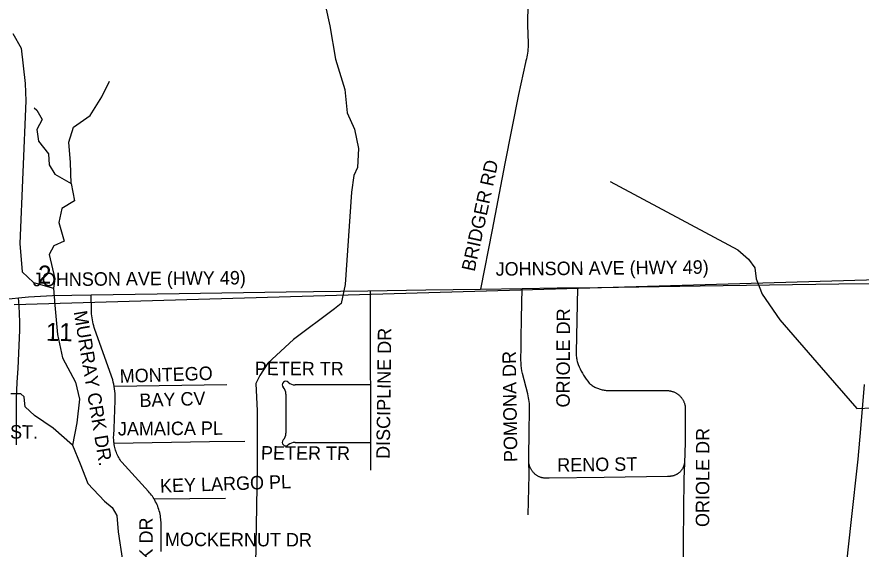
# Model space of a CAD drawing. Extents: x 1670563 to 1761545, y 515755 to 578944.
# Drawn here: x 1715137 to 1719841, y 558581 to 561545 of the extents above; entities that cross this region are included whole.
import ezdxf

# ---------------------------------------------------------------- set-up
doc = ezdxf.new("R2010")
doc.units = 0
for name, color, linetype in [('5_sectionlines', 7, 'Continuous'), ('62_text', 7, 'Continuous'), ('SHP_LINE', 7, 'Continuous'), ('STREETCL', 7, 'Continuous'), ('STRNAMES', 7, 'Continuous')]:
    doc.layers.add(name, color=color, linetype=linetype)

msp = doc.modelspace()

# ---------------------------------------------------------------- linework, layer by layer
at = {"layer": '5_sectionlines'}
msp.add_lwpolyline([(1715121.2, 559943.8), (1720383.9, 560096.2), (1725635, 560117.2)], dxfattribs=at)
at = {"layer": 'SHP_LINE'}
for points in [[(1716829, 561733), (1716881, 561495), (1716913, 561309), (1716965, 561140), (1716977, 561011), (1717018, 560920), (1717040, 560812), (1717035, 560706), (1717014, 560661), (1717001, 560568), (1716966, 560055), (1716944, 559949), (1716907, 559919), (1716678, 559748), (1716535, 559616), (1716490, 559547), (1716468, 559504), (1716476, 559352), (1716476, 559038), (1716456, 557842)], [(1715114, 561452), (1715161, 561370), (1715183, 561174), (1715188, 561078), (1715153, 560282), (1715166, 560125), (1715230, 560066), (1715342, 560035)], [(1715440, 560617), (1715436, 560734), (1715427, 560847), (1715453, 560930), (1715545, 560995), (1715610, 561100), (1715654, 561187)], [(1715233, 561039), (1715249, 561026), (1715279, 560974), (1715249, 560917), (1715257, 560852), (1715314, 560782), (1715318, 560721), (1715349, 560669), (1715440, 560617)], [(1715440, 560617), (1715458, 560521), (1715388, 560477), (1715371, 560399), (1715401, 560295), (1715344, 560269), (1715318, 560221), (1715349, 560086), (1715342, 560035)], [(1718442, 560629), (1719154, 560248), (1719214, 560196), (1719248, 560147), (1719256, 560087), (1719290, 560000), (1719388, 559857), (1719618, 559593), (1719817, 559364), (1719904, 559368)], [(1715342, 560035), (1715348, 559939), (1715363, 559776), (1715391, 559647), (1715464, 559511), (1715487, 559417), (1715471, 559285), (1715448, 559160)], [(1715448, 559160), (1715339, 559255), (1715236, 559325), (1715183, 559373), (1715179, 559408), (1715178, 559430), (1715159, 559445), (1715104, 559445)], [(1715448, 559160), (1715489, 559056), (1715533, 558946), (1715625, 558849), (1715669, 558813), (1715694, 558769), (1715702, 558677), (1715726, 558518), (1715752, 558442), (1715750, 558388), (1715770, 558340), (1715754, 558253), (1715745, 558154), (1715781, 558044), (1715853, 557990), (1715937, 557973), (1715999, 557974), (1716056, 557940), (1716130, 557887), (1716243, 557864), (1716330, 557869), (1716391, 557866), (1716456, 557842)]]:
    msp.add_lwpolyline(points, dxfattribs=at)
at = {"layer": 'STREETCL'}
for points in [[(1717986.7, 561877.2), (1717982.5, 561498.3), (1717985.3, 561397.7), (1717985.4, 561386.8), (1717985.1, 561375.8), (1717984.5, 561364.9), (1717983.5, 561354.1), (1717982.2, 561343.2), (1717980.5, 561332.5), (1717978.4, 561321.7), (1717975.9, 561311.1), (1717973.1, 561300.6), (1717970, 561290.1), (1717932.5, 561112.4), (1717856, 560728.7), (1717785.7, 560358.8), (1717720.8, 560029)], [(1717092.5, 560020), (1717415.9, 560024.7), (1717720.8, 560029)], [(1717720.8, 560029), (1717952.4, 560032.4)], [(1717989.1, 559074.8), (1717991.2, 559250.6), (1717992.9, 559336.1), (1717993.4, 559347.2), (1717993.6, 559358.2), (1717993.5, 559369.3), (1717993.1, 559380.4), (1717992.3, 559391.5), (1717991.2, 559402.5), (1717989.7, 559413.5), (1717987.8, 559424.4), (1717985.6, 559435.3), (1717983.1, 559446.1), (1717953.6, 559559.2), (1717950.9, 559573.9), (1717948.7, 559588.6), (1717946.9, 559603.4), (1717945.8, 559618.2), (1717945.1, 559633.1), (1717944.9, 559648), (1717945.2, 559662.9), (1717946.1, 559677.7), (1717946.7, 559754), (1717947.8, 559864.4), (1717952.4, 560032.4)], [(1717952.4, 560032.4), (1718147.5, 560035.2), (1718259.7, 560036.7)], [(1718259.7, 560036.7), (1718252.9, 559675.4), (1718252.9, 559669.3), (1718253.1, 559663.1), (1718253.5, 559656.9), (1718254.2, 559650.8), (1718255, 559644.7), (1718256.1, 559638.6), (1718257.3, 559632.6), (1718258.8, 559626.6), (1718260.5, 559620.7), (1718262.4, 559614.8), (1718264.5, 559609), (1718269.7, 559596.7), (1718275.3, 559584.6), (1718281.3, 559572.6), (1718287.7, 559560.9), (1718294.5, 559549.4), (1718301.7, 559538.1), (1718309.2, 559527.1), (1718317.2, 559516.4), (1718325.4, 559505.9), (1718329.6, 559502.3), (1718333.8, 559498.8), (1718338.2, 559495.4), (1718342.7, 559492.3), (1718347.3, 559489.2), (1718352, 559486.4), (1718356.7, 559483.7), (1718361.6, 559481.1), (1718366.6, 559478.8), (1718371.6, 559476.6), (1718376.8, 559474.6), (1718381.9, 559472.8), (1718387.2, 559471.1), (1718392.5, 559469.7), (1718397.8, 559468.4), (1718403.2, 559467.3), (1718408.6, 559466.4), (1718414.1, 559465.7), (1718419.6, 559465.2), (1718425, 559464.8), (1718430.5, 559464.7), (1718760.3, 559464), (1718763.9, 559463.8), (1718767.4, 559463.6), (1718770.9, 559463.2), (1718774.4, 559462.8), (1718777.8, 559462.2), (1718781.3, 559461.4), (1718784.7, 559460.6), (1718788.1, 559459.6), (1718791.5, 559458.6), (1718794.8, 559457.4), (1718798.1, 559456.1), (1718801.3, 559454.7), (1718804.5, 559453.2), (1718807.6, 559451.5), (1718810.6, 559449.8), (1718813.7, 559448), (1718816.6, 559446), (1718819.5, 559444), (1718822.3, 559441.9), (1718825, 559439.6), (1718827.6, 559437.3), (1718830.2, 559434.9), (1718832.7, 559432.4), (1718835.1, 559429.8), (1718837.4, 559427.2), (1718839.6, 559424.4), (1718841.7, 559421.6), (1718843.7, 559418.7), (1718845.7, 559415.8), (1718847.5, 559412.7), (1718849.2, 559409.7), (1718850.8, 559406.5), (1718852.3, 559403.3), (1718853.7, 559400.1), (1718855, 559396.8), (1718856.1, 559393.5), (1718857.2, 559390.1), (1718858.1, 559386.7), (1718858.9, 559383.3), (1718859.6, 559379.9), (1718860.2, 559376.4), (1718860.7, 559372.9), (1718861, 559369.4), (1718861.2, 559365.9), (1718861.2, 559250.4), (1718859.5, 559174.7), (1718856.2, 559059.5)], [(1718259.7, 560036.7), (1718944, 560046.4), (1719715.7, 560057.7), (1719906.5, 560060.3)], [(1712480.7, 558684.6), (1712572.9, 558740.6), (1712940.5, 558965.5), (1713388.6, 559240.4), (1713771.7, 559474.8), (1714010.2, 559617.7), (1714063.8, 559648.6), (1714118.5, 559677.9), (1714174, 559705.3), (1714230.4, 559730.9), (1714287.6, 559754.7), (1714403.4, 559798.6), (1714520.5, 559839.1), (1714638.7, 559876.1), (1714758, 559909.6), (1714878.2, 559939.6), (1714910.1, 559946.5), (1714942.2, 559952.4), (1714974.5, 559957.3), (1715007, 559961.1), (1715076.4, 559972.2), (1715146.1, 559980.9)], [(1715134.4, 559161.9), (1715135.1, 559208.4), (1715134.4, 559371.3), (1715134.8, 559417.8), (1715136.5, 559464.3), (1715139.4, 559510.7), (1715143.7, 559586.8), (1715153.1, 559800.7), (1715153.7, 559845.8), (1715152.7, 559890.9), (1715150.2, 559936), (1715146.1, 559980.9)], [(1715146.1, 559980.9), (1715201.3, 559986.2), (1715336.5, 559993.4), (1715550.7, 559997.1)], [(1715550.7, 559997.1), (1716041.6, 560005.4), (1716637.9, 560013.5), (1717092.5, 560020)], [(1715679.4, 559486.6), (1715677.1, 559499.1), (1715674.4, 559511.6), (1715671.4, 559523.9), (1715572.2, 559803.7), (1715568.6, 559814.4), (1715565.4, 559825.2), (1715562.5, 559836.1), (1715560, 559847.1), (1715557.8, 559858.1), (1715556, 559869.3), (1715554.6, 559880.5), (1715553.5, 559891.7), (1715552.8, 559902.9), (1715552.5, 559914.2), (1715550.7, 559997.1)], [(1717109.7, 559021.6), (1717107.2, 560020.1)], [(1716649.5, 559510.4), (1716649.5, 559510.4)], [(1715678.5, 559170.4), (1715677.6, 559177.5), (1715677, 559184.7), (1715676.6, 559191.9), (1715676.4, 559199.1), (1715676.4, 559206.3), (1715676.7, 559213.4), (1715679.1, 559251.9), (1715685, 559409.3), (1715685, 559422.2), (1715684.7, 559435.1), (1715684, 559448), (1715682.9, 559460.9), (1715681.3, 559473.8), (1715679.4, 559486.6)], [(1716307.1, 559496.7), (1715679.4, 559486.6)], [(1716621.2, 559482.2), (1716621.2, 559482.2)], [(1717108.6, 559495.8), (1716686.9, 559495.8)], [(1719856.7, 559497.6), (1719837.9, 559251), (1719822.2, 559081.5), (1719783.2, 558728.8), (1719746.4, 558388.8)], [(1716635.9, 559444.8), (1716635.9, 559444.8), (1716635.9, 559226.6), (1716635.9, 559226.6)], [(1715678.5, 559170.4), (1716209.9, 559180.2), (1716407.2, 559182.1)], [(1716621.2, 559189.2), (1716621.2, 559189.2)], [(1715901.2, 558860.8), (1715896.7, 558868), (1715892, 558875.1), (1715887.1, 558881.9), (1715881.9, 558888.7), (1715876.6, 558895.2), (1715871.1, 558901.6), (1715721.3, 559064.8), (1715716.8, 559071), (1715712.6, 559077.4), (1715708.6, 559084), (1715704.8, 559090.6), (1715701.2, 559097.4), (1715697.9, 559104.3), (1715694.7, 559111.3), (1715691.9, 559118.5), (1715689.2, 559125.7), (1715686.8, 559132.9), (1715684.7, 559140.3), (1715682.8, 559147.7), (1715681.1, 559155.2), (1715679.7, 559162.8), (1715678.5, 559170.4)], [(1716649.5, 559161), (1716649.5, 559161)], [(1716686.9, 559175.6), (1716686.9, 559175.6), (1717109.4, 559175.6)], [(1717985.8, 558772.8), (1717991.2, 558994.6), (1717989.1, 559074.8)], [(1718856.2, 559059.5), (1718855.7, 559056.5), (1718855.1, 559053.6), (1718854.4, 559050.7), (1718853.5, 559047.8), (1718852.6, 559045), (1718851.6, 559042.1), (1718850.5, 559039.3), (1718849.3, 559036.6), (1718848, 559033.9), (1718846.6, 559031.2), (1718845.1, 559028.6), (1718843.5, 559026.1), (1718841.8, 559023.6), (1718840.1, 559021.2), (1718838.3, 559018.8), (1718836.4, 559016.5), (1718834.4, 559014.2), (1718832.3, 559012), (1718830.2, 559009.9), (1718828, 559007.9), (1718825.7, 559005.9), (1718823.3, 559004.1), (1718820.9, 559002.3), (1718818.5, 559000.6), (1718816, 558999), (1718813.4, 558997.4), (1718810.7, 558996), (1718808.1, 558994.6), (1718805.4, 558993.3), (1718802.6, 558992.2), (1718799.8, 558991.1), (1718797, 558990.1), (1718794.1, 558989.3), (1718791.2, 558988.5), (1718788.3, 558987.8), (1718785.3, 558987.2), (1718782.4, 558986.7), (1718779.4, 558986.4), (1718776.4, 558986.1), (1718773.4, 558985.9), (1718770.4, 558985.8), (1718767.4, 558985.9), (1718764.4, 558986), (1718761.4, 558986.3), (1718408.2, 558980), (1718103.3, 558976.8), (1718099.9, 558976.3), (1718096.5, 558975.9), (1718093.1, 558975.7), (1718089.6, 558975.5), (1718086.2, 558975.5), (1718082.8, 558975.6), (1718079.3, 558975.8), (1718075.9, 558976.1), (1718072.5, 558976.6), (1718069.2, 558977.2), (1718065.8, 558977.8), (1718062.5, 558978.7), (1718059.2, 558979.6), (1718055.9, 558980.6), (1718052.7, 558981.8), (1718049.5, 558983), (1718046.3, 558984.4), (1718043.2, 558985.9), (1718040.2, 558987.5), (1718037.2, 558989.2), (1718034.3, 558991), (1718031.4, 558992.9), (1718028.6, 558994.9), (1718025.9, 558997), (1718023.3, 558999.1), (1718020.7, 559001.4), (1718018.2, 559003.8), (1718015.8, 559006.2), (1718013.5, 559008.8), (1718011.3, 559011.4), (1718009.2, 559014.1), (1718007.1, 559016.8), (1718005.2, 559019.7), (1718003.4, 559022.6), (1718001.6, 559025.5), (1718000, 559028.5), (1717998.5, 559031.6), (1717997.1, 559034.7), (1717995.8, 559037.9), (1717994.6, 559041.1), (1717993.5, 559044.4), (1717992.5, 559047.7), (1717991.7, 559051), (1717991, 559054.4), (1717990.3, 559057.7), (1717989.9, 559061.1), (1717989.5, 559064.5), (1717989.2, 559068), (1717989.1, 559071.4), (1717989.1, 559074.8)], [(1718856.2, 559059.5), (1718853.3, 558972.9), (1718847.9, 558449.6)], [(1715901.2, 558860.8), (1716300.2, 558865.1)], [(1715940.4, 558567.1), (1715940.4, 558574), (1715940.4, 558702.9), (1715940.8, 558712.1), (1715940.9, 558721.3), (1715940.6, 558730.4), (1715940.1, 558739.6), (1715939.2, 558748.7), (1715938.1, 558757.8), (1715936.6, 558766.9), (1715934.8, 558775.9), (1715932.8, 558784.8), (1715930.4, 558793.7), (1715927.7, 558802.5), (1715924.8, 558811.2), (1715921.6, 558819.8), (1715918, 558828.3), (1715914.2, 558836.6), (1715910.2, 558844.8), (1715905.8, 558852.9), (1715901.2, 558860.8)]]:
    msp.add_lwpolyline(points, dxfattribs=at)
for centre, radius, start, end in [((1716635.9, 559495.8), 20, 47.1666, 222.8334), ((1716686.9, 559550.8), 55, 227.1666, 270), ((1716580.9, 559444.8), 55, 0, 42.8334), ((1716635.9, 559175.6), 20, 137.1666, 312.8334), ((1716580.9, 559226.6), 55, 317.1666, 360), ((1716686.9, 559120.6), 55, 90, 132.8334)]:
    msp.add_arc(centre, radius, start, end, dxfattribs=at)

# ---------------------------------------------------------------- texts
at = {"layer": '62_text'}
for s, rotation, p in [('2', 358.9283, (1715253.9, 560060.4)), ('11', 358.9284, (1715297.9, 559741.4))]:
    msp.add_text(s, height=100, rotation=rotation, dxfattribs=at).set_placement(p)
at = {"layer": 'STRNAMES'}
for s, rotation, p in [('BRIDGER RD', 77.7738, (1717687, 560123.4)), ('JOHNSON AVE (HWY 49)', 0.5603, (1717804.8, 560103.3)), ('JOHNSON AVE (HWY 49)', 0.53, (1715226.3, 560044.4)), ('MURRAY CRK DR.', 279.4393, (1715453.2, 559902.6)), ('ORIOLE DR', 89.8308, (1718217.4, 559369.8)), ('DISCIPLINE DR', 89.3, (1717214.6, 559082.9)), ('POMONA DR', 90.8308, (1717925.8, 559066.5)), ('PETER TR', 359.7808, (1716462.2, 559550.1)), ('MONTEGO ', 1.9151, (1715711.4, 559506.7)), ('BAY CV', 1.9151, (1715821.5, 559371.6)), ('JAMAICA PL', 0.3902, (1715700.1, 559213.7)), ('BRENDA ST.', 359.8288, (1714653.3, 559197.9)), ('ORIOLE DR', 89.8308, (1718994.2, 558704)), ('PETER TR', 359.7808, (1716497.2, 559079.7)), ('RENO ST', 0.8308, (1718148.2, 559012)), ('KEY LARGO PL', 1.9151, (1715935.7, 558895.7)), ('MURRAY CRK DR', 89.7808, (1715891.4, 557910)), ('MOCKERNUT DR', 359.7808, (1715961.9, 558598.4))]:
    msp.add_text(s, height=75, rotation=rotation, dxfattribs=at).set_placement(p)

doc.saveas('drawing.dxf')
